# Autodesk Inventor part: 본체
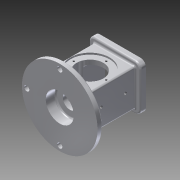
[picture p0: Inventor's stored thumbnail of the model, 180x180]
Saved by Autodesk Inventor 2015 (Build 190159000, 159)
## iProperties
Created: 2019-08
Part Number: 본체
Material: 알루미늄 6061
Document SubType Name: Modeling
Designer: a5
Density: 2.7 g/cm^3
Appearance: 알루미늄 - 평지
Mass: 1038.83 g
Surface Area: 783.574 cm^2
Volume: 384.751 cm^3
Author: a5
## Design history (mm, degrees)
sketch "스케치1"
  geometry: L1 (37, -33)-(-37, -33); L2 (-37, -33)-(-37, 33); L3 (-37, 33)-(37, 33); L4 (37, 33)-(37, -33); 3 further points
  constraints: 8 end point, 2 midpoint, 2 parallel, 1 horizontal, 1 horizontal alignment, 1 perpendicular, 1 vertical alignment
  dimensions: "d0" = 74 distance of L2.end L3.end; "d1" = 66 distance of L1.end L2.end
extrude "돌출1" new body sketch "스케치1" stored distance "d2" = 108; taper "d3" = 0 deg
sketch "스케치2"
  geometry: C1 r 67.5 at (0, 0); C2 r 4.5 at (0, 59); C3 r 4.5 at (0, -59); C4 r 4.5 at (-59, 0); 1 further point
  constraints: 4 centre point, 2 vertical alignment, 1 coincident, 1 horizontal alignment
  dimensions: "d4" = 67.5 radius of C1; "d5" = 4.5 radius of C2; "d6" = 4.5 radius of C3; "d7" = 4.5 radius of C4; "d8" = 118 distance of C3.centre C2.centre; "d9" = 59 distance of point (0, 0) C2.centre; "d10" = 59 distance of C4.centre point (0, 0)
extrude "돌출2" join sketch "스케치2" distance "d11" = 10; taper "d12" = 0 deg
sketch "스케치3"
  geometry: L1 (-46, -41)-(46, -41); L2 (46, -41)-(46, 41); L3 (46, 41)-(-46, 41); L4 (-46, 41)-(-46, -41); 3 further points
  constraints: 8 end point, 2 midpoint, 2 parallel, 1 horizontal, 1 horizontal alignment, 1 perpendicular, 1 vertical alignment
  dimensions: "d13" = 92 distance of L3.end L2.end; "d14" = 82 distance of L2.end L1.end
extrude "돌출3" join sketch "스케치3" distance "d15" = 10; taper "d16" = 0 deg
sketch "스케치4"
  geometry: C1 r 35 at (37, 44); 1 further point
  constraints: 1 centre point, 1 coincident
  dimensions: "d17" = 35 radius of C1
extrude "돌출4" cut sketch "스케치4" distance "d18" = 3; taper "d19" = 0 deg
sketch "스케치5"
  geometry: C1 r 24 at (0, 0); 1 further point
  constraints: 1 centre point, 1 coincident
  dimensions: "d20" = 24 radius of C1
extrude "돌출5" cut sketch "스케치5" distance "d21" = 40; taper "d22" = 0 deg
sketch "스케치7"
  geometry: L1 (-26, -26)-(26, -26); L2 (26, -26)-(26, 26); L3 (26, 26)-(-26, 26); L4 (-26, 26)-(-26, -26); 3 further points
  constraints: 8 end point, 2 midpoint, 2 parallel, 1 horizontal, 1 horizontal alignment, 1 perpendicular, 1 vertical alignment
  dimensions: "d34" = 52 distance of L3.end L2.end; "d35" = 52 distance of L2.end L1.end
extrude "돌출6" cut sketch "스케치7" distance "d36" = 8; taper "d37" = 0 deg
sketch "스케치8"
  geometry: L1 (-22, -22)-(22, -22); L2 (22, -22)-(22, 22); L3 (22, 22)-(-22, 22); L4 (-22, 22)-(-22, -22); 3 further points
  constraints: 8 end point, 2 midpoint, 2 parallel, 1 horizontal, 1 horizontal alignment, 1 perpendicular, 1 vertical alignment
  dimensions: "d38" = 44 distance of L3.end L2.end; "d39" = 44 distance of L2.end L1.end
extrude "돌출7" cut sketch "스케치8" distance "d40" = 74; taper "d41" = 0 deg
sketch "스케치9"
  geometry: C1 r 25 at (0, 0); 1 further point
  constraints: 1 centre point, 1 coincident
  dimensions: "d42" = 25 radius of C1
extrude "돌출8" cut sketch "스케치9" distance "d43" = 18; taper "d44" = 0 deg
sketch "스케치10"
  geometry: C1 r 12.5 at (0, 0); 1 further point
  constraints: 1 centre point, 1 coincident
  dimensions: "d45" = 12.5 radius of C1
extrude "돌출9" cut sketch "스케치10" stored distance "d46" = 18; taper "d47" = 0 deg
sketch "스케치11"
  geometry: L1 (100.5, -10)-(-34.5, -10) reference; 3 further points
  constraints: 2 vertical alignment
  dimensions: "d48" = 37 distance from line of L1 point (33, 27); "d49" = 43 distance of point (33, 70) point (33, 27)
hole "구멍2" sketch "스케치11" at (33, 70), (33, 27) diameter "d50" = 4.917; stored, may be unused: countersink angle "d54" = 90 deg, drill point angle "d56" = 118 deg; dims "d51" = 30, "d52" = 4, "d53" = 2, "d55" = 30
sketch "스케치12"
  geometry: C1 r 59 at (0, 0); 1 further point
  constraints: 1 centre point, 1 coincident, 1 other
  dimensions: "d57" = 59 radius of C1
feature "엠보싱1" sketch "스케치12" dims "d0" = 74, "d1" = 66, "d13" = 92, "d14" = 82, "d58" = 0.5, "d59" = 0
chamfer "모따기1" distance "d60" = 3; stored, may be unused: second distance "d61" = 2, angle "d62" = 45 deg
fillet "모깎기1" dims "d63" = 3
fillet "모깎기2" dims "d64" = 3
fillet "모깎기3" dims "d65" = 10
fillet "모깎기4" dims "d66" = 3
chamfer "모따기2" distance "d67" = 1; stored, may be unused: second distance "d68" = 2, angle "d69" = 45 deg
fillet "모깎기5" dims "d70" = 3
fillet "모깎기6" dims "d71" = 3
sketch "스케치6"
  geometry: 5 further points
  constraints: 2 horizontal alignment, 2 vertical alignment
  dimensions: "d23" = 29 distance of point (0, 0) point (0, 29); "d86" = 29 distance of point (0, 0) point (-29, 0); "d87" = 58 distance of point (0, -29) point (0, 29); "d88" = 58 distance of point (-29, 0) point (29, 0)
hole "구멍5" sketch "스케치6" at (0, 29), (0, -29), (-29, 0), (29, 0) diameter "d89" = 3.242; stored, may be unused: countersink angle "d93" = 90 deg, drill point angle "d95" = 118 deg; dims "d90" = 4, "d91" = 4, "d92" = 2, "d94" = 6
sketch "스케치13"
  geometry: L1 (36, 41)-(-36, 41) reference; L2 (-46, 31)-(-46, -31) reference; L3 (-36, -41)-(36, -41) reference; L4 (46, -31)-(46, 31) reference; L5 (27, -27)-(27, 27) reference; L6 (-27, -27)-(27, -27) reference; L7 (-27, 27)-(-27, -27) reference; L8 (27, 27)-(-27, 27) reference; A1 r 10 centre (36, 31) between (46, 31) and (36, 41) reference; A2 r 10 centre (-36, 31) between (-36, 41) and (-46, 31) reference; A3 r 10 centre (-36, -31) between (-46, -31) and (-36, -41) reference; A4 r 10 centre (36, -31) between (36, -41) and (46, -31) reference; 5 further points
  constraints: 4 coincident
hole "구멍6" sketch "스케치13" at (-36, -31), (36, -31), (36, 31), (-36, 31) diameter "d96" = 3.242; stored, may be unused: countersink angle "d100" = 90 deg, drill point angle "d102" = 118 deg; dims "d97" = 4, "d98" = 4, "d99" = 2, "d101" = 6
node "솔리드1"
mirror "대칭2"
node "투영된 루프1"
